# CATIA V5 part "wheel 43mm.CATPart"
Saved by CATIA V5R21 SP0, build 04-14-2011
Part number: wheel 43mm
Definition: wheel 43mm
Nomenclature: wheel 43mm
Source: Unknown
Bounding box of the stored display mesh (mm): x -21.5 to 21.5, y -18 to 0, z -21.499 to 21.499
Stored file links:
  C:\Users\beatr\OneDrive\Documents\UNB\2026_1\Pi1\Componentes eletronicos\Roda\wheel 43mm.CATPart
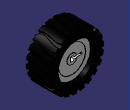
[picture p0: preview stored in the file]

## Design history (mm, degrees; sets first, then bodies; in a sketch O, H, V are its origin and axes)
Body1 "Solid1" (main body)
  Solid1: solid without history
